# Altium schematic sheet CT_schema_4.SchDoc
size 145 x 123 mm
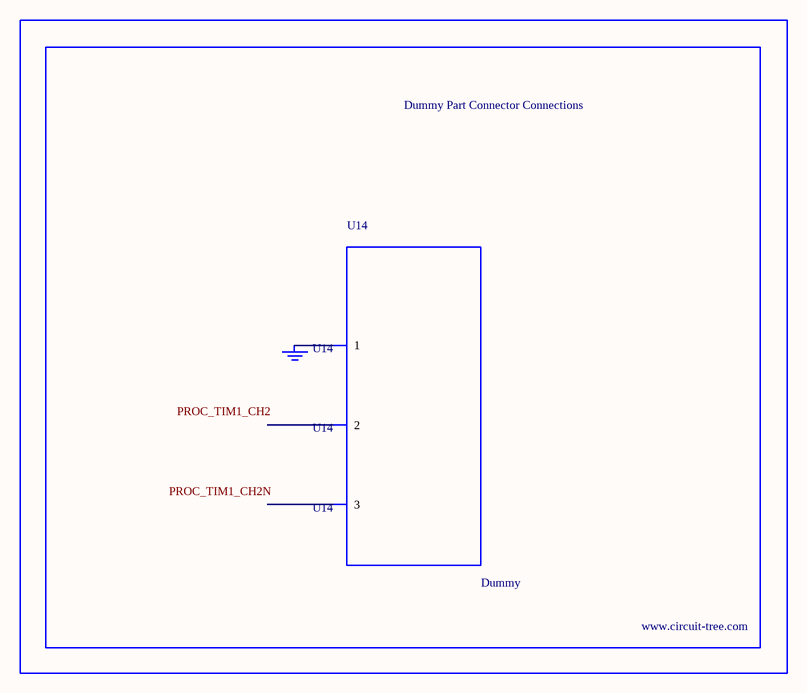
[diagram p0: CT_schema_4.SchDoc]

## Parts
BORDER3  (no value)
GND_INSTANCE_3_0  (no value)
U14  Dummy  [DUMMY_PACKAGE_135]

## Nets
NetGND_INSTANCE_3_0_0: GND_INSTANCE_3_0.0(GND) U14.1

Not connected (* = marked no-connect by the designer): U14 2 3

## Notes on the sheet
- Labels drawn without touching a wire or pin: PROC_TIM1_CH2, PROC_TIM1_CH2N

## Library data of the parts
BORDER3 = BORDER_PAGE3
GND_INSTANCE_3_0 = GND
